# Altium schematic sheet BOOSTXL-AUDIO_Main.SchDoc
size 431 x 279 mm; Date: Not shown in title block; ApprovedBy: Not shown in title block; CheckedBy: Not shown in title block; Author: Not shown in title block; CompanyName: Not shown in title block; Engineer: Not shown in title block; Organization: Not shown in title block; Address1: Not shown in title block; Address2: Not shown in title block; Address3: Not shown in title block; Address4: Not shown in title block; DocumentNumber: 1; Revision: Use project parameter SCH_Rev; SheetNumber: 1; SheetTotal: 2; PageSetup: Record=PageOptions¦CenterHorizontal=True¦CenterVertical=True¦PrintScale=0.62¦XCorrection=1.00¦YCorrection=1.00¦PrintKind=0¦BorderSize=5000000¦LeftOffset=0¦BottomOffset=0¦Orientation=2¦PaperLength=1000¦PaperWidth=1000¦Scale=100¦PaperSource=15¦PrintQuality=600¦MediaType=1¦DitherType=10¦PrintScaleMode=1¦PaperKind=Letter
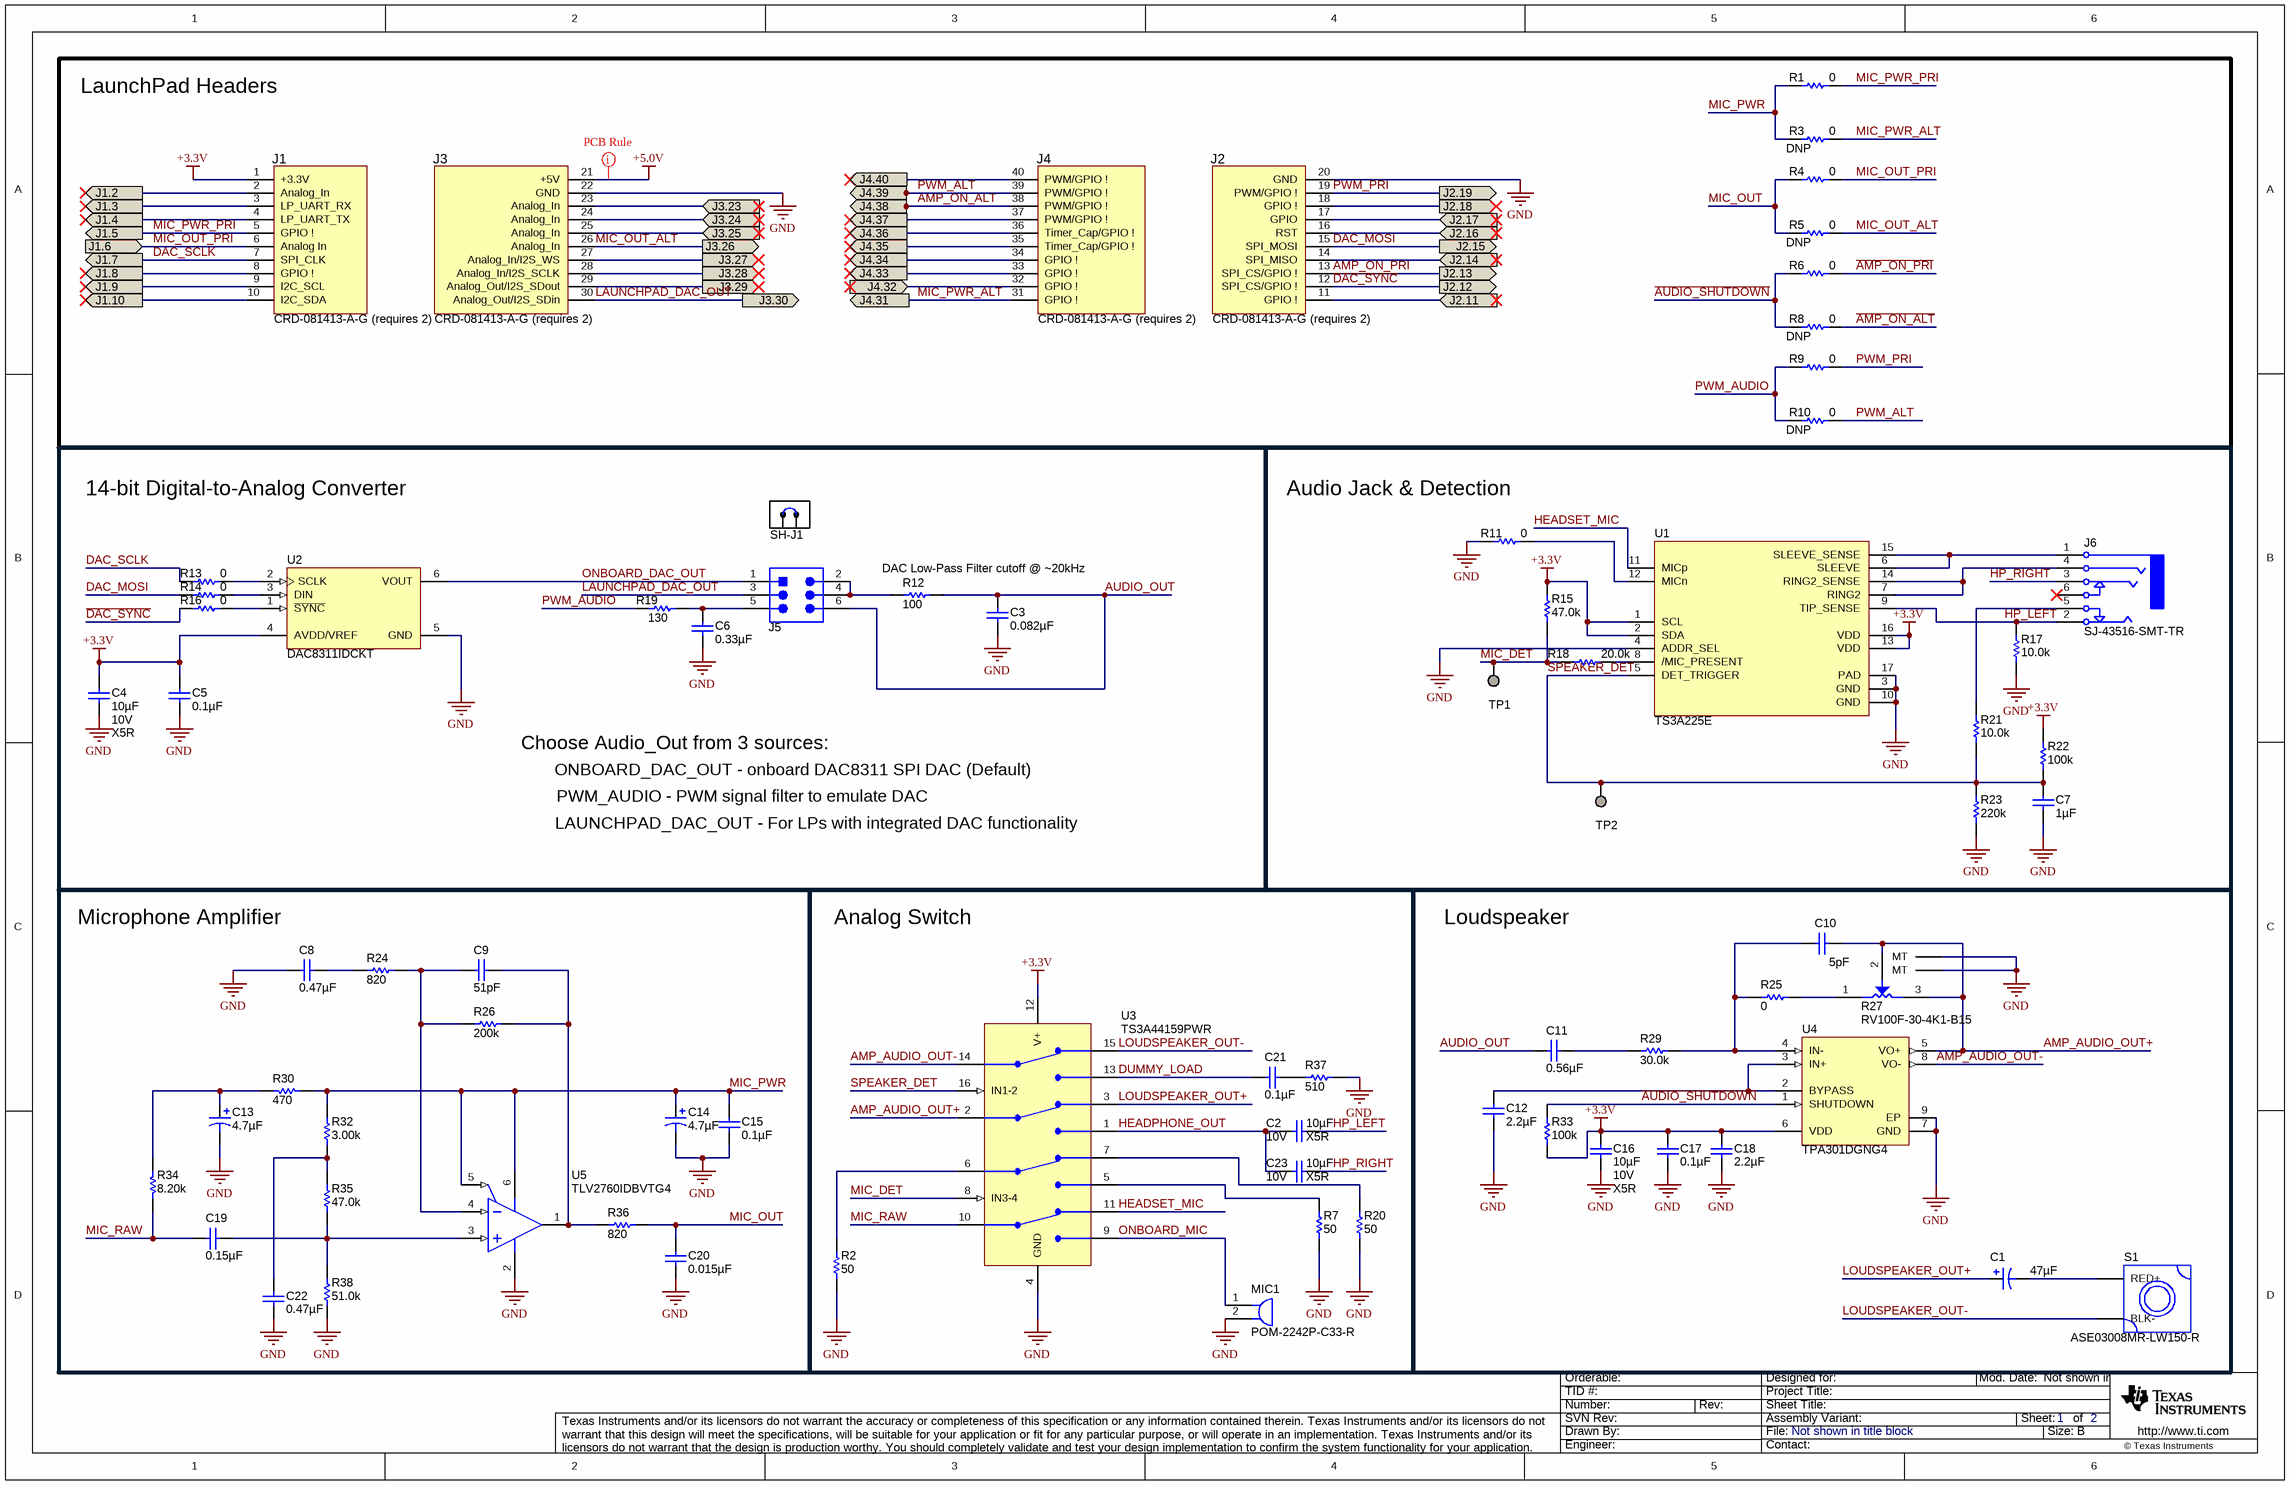
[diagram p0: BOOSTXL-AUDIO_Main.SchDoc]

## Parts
C1  ValueDisplayed: 47µF  [3528-21]  (hidden comment: TPSB476K010R0250)
C2  ValueDisplayed: 10µF  Value2: 10V  TempCo: X5R  [0603]  (hidden comment: C1608X5R1A106M)
C3  ValueDisplayed: 0.082µF  [0603]  (hidden comment: GRM188R71C823KA01D)
C4  ValueDisplayed: 10µF  Value2: 10V  TempCo: X5R  [0603]  (hidden comment: C1608X5R1A106M)
C5  ValueDisplayed: 0.1µF  [0603]  (hidden comment: GRM188R70J104KA01D)
C6  ValueDisplayed: 0.33µF  [0603]  (hidden comment: C0603C334K8RACTU)
C7  ValueDisplayed: 1µF  [0603]  (hidden comment: GRM188R71C105KA12D)
C8  ValueDisplayed: 0.47µF  [0603]  (hidden comment: GRM188R60J474KA01D)
C9  ValueDisplayed: 51pF  [0603]  (hidden comment: GRM1885C2A510JA01D)
C10  ValueDisplayed: 5pF  [0603]  (hidden comment: CC0603CRNPO9BN5R0)
C11  ValueDisplayed: 0.56µF  [0603]  (hidden comment: GRM188R71A564KA61D)
C12  ValueDisplayed: 2.2µF  [0603]  (hidden comment: GRM188R61A225KE34D)
C13  ValueDisplayed: 4.7µF  [3216-18]  (hidden comment: TPSA475K010R1400)
C14  ValueDisplayed: 4.7µF  [3216-18]  (hidden comment: TPSA475K010R1400)
C15  ValueDisplayed: 0.1µF  [0603]  (hidden comment: GRM188R70J104KA01D)
C16  ValueDisplayed: 10µF  Value2: 10V  TempCo: X5R  [0603]  (hidden comment: C1608X5R1A106M)
C17  ValueDisplayed: 0.1µF  [0603]  (hidden comment: GRM188R70J104KA01D)
C18  ValueDisplayed: 2.2µF  [0603]  (hidden comment: GRM188R61A225KE34D)
C19  ValueDisplayed: 0.15µF  [0603]  (hidden comment: GRM188R61A154KA01D)
C20  ValueDisplayed: 0.015µF  [0603]  (hidden comment: C0603C153K1RACTU)
C21  ValueDisplayed: 0.1µF  [0603]  (hidden comment: GRM188R70J104KA01D)
C22  ValueDisplayed: 0.47µF  [0603]  (hidden comment: GRM188R60J474KA01D)
C23  ValueDisplayed: 10µF  Value2: 10V  TempCo: X5R  [0603]  (hidden comment: C1608X5R1A106M)
J1  CRD-081413-A-G (requires 2)  [40Pin BP]  (parts A,B,C,D of 4)
J5  PBC03DAAN  [Sullins_PBC03DAAN]  (value not drawn)
J6  SJ-43516-SMT-TR  [CUI_SJ-43516-SMT]
MIC1  POM-2242P-C33-R  [MIC_POM-2242P-C33-R]
R1  ValueDisplayed: 0  [0603]  (hidden comment: CRCW06030000Z0EA)
R2  ValueDisplayed: 50  [0603]  (hidden comment: CRCW060350R0FKEA)
R3  ValueDisplayed: 0  [0603]  (hidden comment: CRCW06030000Z0EA)
R4  ValueDisplayed: 0  [0603]  (hidden comment: CRCW06030000Z0EA)
R5  ValueDisplayed: 0  [0603]  (hidden comment: CRCW06030000Z0EA)
R6  ValueDisplayed: 0  [0603]  (hidden comment: CRCW06030000Z0EA)
R7  ValueDisplayed: 50  [0603]  (hidden comment: CRCW060350R0FKEA)
R8  ValueDisplayed: 0  [0603]  (hidden comment: CRCW06030000Z0EA)
R9  ValueDisplayed: 0  [0603]  (hidden comment: CRCW06030000Z0EA)
R10  ValueDisplayed: 0  [0603]  (hidden comment: CRCW06030000Z0EA)
R11  ValueDisplayed: 0  [0603]  (hidden comment: CRCW06030000Z0EA)
R12  ValueDisplayed: 100  [0603]  (hidden comment: RC0603FR-07100RL)
R13  ValueDisplayed: 0  [0603]  (hidden comment: CRCW06030000Z0EA)
R14  ValueDisplayed: 0  [0603]  (hidden comment: CRCW06030000Z0EA)
R15  ValueDisplayed: 47.0k  [0603]  (hidden comment: RC0603FR-0747KL)
R16  ValueDisplayed: 0  [0603]  (hidden comment: CRCW06030000Z0EA)
R17  ValueDisplayed: 10.0k  [0603]  (hidden comment: RC0603FR-0710KL)
R18  ValueDisplayed: 20.0k  [0603]  (hidden comment: RC0603FR-0720KL)
R19  ValueDisplayed: 130  [0603]  (hidden comment: RC0603FR-07130RL)
R20  ValueDisplayed: 50  [0603]  (hidden comment: CRCW060350R0FKEA)
R21  ValueDisplayed: 10.0k  [0603]  (hidden comment: RC0603FR-0710KL)
R22  ValueDisplayed: 100k  [0603]  (hidden comment: CRCW0603100KFKEA)
R23  ValueDisplayed: 220k  [0603]  (hidden comment: RC0603FR-07220KL)
R24  value 820  [0603]  (hidden comment: RC0603FR-07820RL)
R25  ValueDisplayed: 0  [0603]  (hidden comment: CRCW06030000Z0EA)
R26  ValueDisplayed: 200k  [0603]  (hidden comment: RC0603FR-07200KL)
R27  RV100F-30-4K1-B15  [RV100F-30-4K1-B15]
R29  ValueDisplayed: 30.0k  [0603]  (hidden comment: RC0603FR-0730KL)
R30  value 470  [0603]  (hidden comment: RC0603FR-07470RL)
R32  ValueDisplayed: 3.00k  [0603]  (hidden comment: RC0603FR-073KL)
R33  ValueDisplayed: 100k  [0603]  (hidden comment: CRCW0603100KFKEA)
R34  value 8.20k  [0603]  (hidden comment: RC0603FR-078K2L)
R35  ValueDisplayed: 47.0k  [0603]  (hidden comment: RC0603FR-0747KL)
R36  value 820  [0603]  (hidden comment: RC0603FR-07820RL)
R37  ValueDisplayed: 510  [0603]  (hidden comment: RC0603FR-07510RL)
R38  ValueDisplayed: 51.0k  [0603]  (hidden comment: RC0603FR-0751KL)
S1  ASE03008MR-LW150-R  [ASE03008MR-LW150-R]
SH-J1  969102-0000-DA  [SNT-100-BK-G]  (value not drawn)
TP1  TESTPOINT  [TP_H045P075]  (value not drawn)  (no BOM)
TP2  TESTPOINT  [TP_H045P075]  (value not drawn)  (no BOM)
U1  TS3A225E  [QFN-16 (RTE)]
U2  DAC8311IDCKT  [TI-DCK6_V]
U3  TS3A44159PWR  [PW0016A_N]
U4  TPA301DGNG4  [TI-DGN8-1760X1425TP_M]
U5  TLV2760IDBVTG4  [DBV0006A_N]

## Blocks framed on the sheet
LaunchPad Headers: J1 R1 R3-R6 R8-R10
14-bit Digital-to-Analog Converter: C3-C6 J5 R12-R14 R16 R19 SH-J1 U2
Audio Jack & Detection: C7 J6 R11 R15 R17 R18 R21-R23 TP1 TP2 U1
Microphone Amplifier: C8 C9 C13-C15 C19 C20 C22 R24 R26 R30 R32 R34-R36 R38 U5
Analog Switch: C2 C21 C23 MIC1 R2 R7 R20 R37 U3
Loudspeaker: C1 C10-C12 C16-C18 R25 R27 R29 R33 S1 U4

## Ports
J1.2, J1.3, J1.4, J1.5 (out), J1.6 (in), J1.7 (out), J1.8, J1.9, J1.10, J2.11, J2.12 (out), J2.13 (out), J2.14, J2.15 (out), J2.16, J2.17, J2.18 (out), J2.19 (out), J3.23, J3.24, J3.25, J3.26 (out), J3.27 (out), J3.28 (out), J3.29 (out), J3.30 (out), J4.31 (out), J4.32 (in), J4.33, J4.34, J4.35, J4.36, J4.37, J4.38 (out), J4.39 (out), J4.40

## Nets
+3.3V: C4.1 C5.1 C16.2 C17.2 C18.1 J1.1(+3.3V) R15.1 R22.1 R33.1 U1.1(SCL) U1.2(SDA) U1.13(VDD) U1.16(VDD) U2.4(AVDD/VREF) U3.12(V+) U4.6(VDD)
+5.0V: J1.21(+5V)
GND: C3.1 C4.2 C5.2 C6.2 C7.1 C8.1 C12.2 C13.2(-) C14.2(-) C15.2 C16.1 C17.1 C18.2 C20.2 C22.1 J1.20(GND) J1.22(GND) MIC1.2 R2.2 R7.2 R11.1 R17.2 R20.2 R23.2 R27.GND(MT) R37.1 R38.1 U1.3(GND) U1.4(ADDR_SEL) U1.10(GND) U1.17(PAD) U2.5(GND) U3.4(GND) U4.7(GND) U4.9(EP) U5.2(GND)
~{AMP_ON_ALT}: J1.38(PWM/GPIO_!) R8.2 ; port J4.38
~{AMP_ON_PRI}: J1.13(SPI_CS/GPIO_!) R6.2 ; port J2.13
~{AUDIO_SHUTDOWN}: R6.1 R8.1 R33.2 U4.1(SHUTDOWN)
~{DAC_SYNC}: J1.12(SPI_CS/GPIO_!) R16.1 ; port J2.12
AMP_AUDIO_OUT+: C10.2 R27.2(A2) R27.3(A3) U3.2(COM2) U4.5(VO+)
AMP_AUDIO_OUT-: U3.14(COM1) U4.8(VO-)
AUDIO_OUT: C3.2 C11.2 J5.6 R12.2
DAC_MOSI: J1.15(SPI_MOSI) R14.1 ; port J2.15
DAC_SCLK: J1.7(SPI_CLK) R13.1 ; port J1.7
DUMMY_LOAD: C21.2 U3.13(NO1)
HEADPHONE_OUT: C2.1 C23.1 U3.1(NO2)
HEADSET_MIC: U1.11(MICp) U3.11(NC4)
HP_LEFT: C2.2 J6.2(TIP) R17.1 U1.9(TIP_SENSE)
HP_RIGHT: C23.2 J6.3(RING_1)
J1.2: J1.2(Analog_In) ; port J1.2
J1.3: J1.3(LP_UART_RX) ; port J1.3
J1.4: J1.4(LP_UART_TX) ; port J1.4
J1.8: J1.8(GPIO_!) ; port J1.8
J1.9: J1.9(I2C_SCL) ; port J1.9
J1.10: J1.10(I2C_SDA) ; port J1.10
J2.11: J1.11(GPIO_!) ; port J2.11
J2.14: J1.14(SPI_MISO) ; port J2.14
J2.16: J1.16(RST) ; port J2.16
J2.17: J1.17(GPIO) ; port J2.17
J2.18: J1.18(GPIO_!) ; port J2.18
J3.23: J1.23(Analog_In) ; port J3.23
J3.24: J1.24(Analog_In) ; port J3.24
J3.25: J1.25(Analog_In) ; port J3.25
J3.27: J1.27(Analog_In/I2S_WS) ; port J3.27
J3.28: J1.28(Analog_In/I2S_SCLK) ; port J3.28
J3.29: J1.29(Analog_Out/I2S_SDout) ; port J3.29
J4.32: J1.32(GPIO_!) ; port J4.32
J4.33: J1.33(GPIO_!) ; port J4.33
J4.34: J1.34(GPIO_!) ; port J4.34
J4.35: J1.35(Timer_Cap/GPIO_!) ; port J4.35
J4.36: J1.36(Timer_Cap/GPIO_!) ; port J4.36
J4.37: J1.37(PWM/GPIO_!) ; port J4.37
J4.40: J1.40(PWM/GPIO_!) ; port J4.40
LAUNCHPAD_DAC_OUT: J1.30(Analog_Out/I2S_SDin) J5.3 ; port J3.30
LOUDSPEAKER_OUT+: C1.1(+) U3.3(NC2)
LOUDSPEAKER_OUT-: S1.2(BLK-) U3.15(NC1)
MIC_DET: R15.2 R18.1 TP1.1 U3.8(IN3-4)
MIC_OUT: C20.1 R4.1 R5.1 R36.2
MIC_OUT_ALT: J1.26(Analog_In) R5.2 ; port J3.26
MIC_OUT_PRI: J1.6(Analog_In) R4.2 ; port J1.6
MIC_PWR: C14.1(+) C15.1 R1.1 R3.1 R30.1 R32.2 U5.5(~{SHDN}) U5.6(VDD)
MIC_PWR_ALT: J1.31(GPIO_!) R3.2 ; port J4.31
MIC_PWR_PRI: J1.5(GPIO_!) R1.2 ; port J1.5
MIC_RAW: C19.1 R34.1 U3.10(COM4)
ONBOARD_DAC_OUT: J5.1 U2.6(VOUT)
ONBOARD_MIC: MIC1.1 U3.9(NO4)
PWM_ALT: J1.39(PWM/GPIO_!) R10.2 ; port J4.39
PWM_AUDIO: R9.1 R10.1 R19.1
PWM_PRI: J1.19(PWM/GPIO_!) R9.2 ; port J2.19
SPEAKER_DET: C7.2 R21.2 R22.2 R23.1 TP2.1 U1.5(DET_TRIGGER) U3.16(IN1-2)
NetC1_2: C1.2(-) S1.1(RED+)
NetC6_1: C6.1 J5.5 R19.2
NetC8_2: C8.2 R24.2
NetC9_1: C9.1 R24.1 R26.1 U5.4(IN-)
NetC9_2: C9.2 R26.2 R36.1 U5.1(OUT)
NetC10_1: C10.1 R25.1 R29.2 U4.4(IN-)
NetC11_1: C11.1 R29.1
NetC12_1: C12.1 U4.2(BYPASS) U4.3(IN+)
NetC13_1: C13.1(+) R30.2 R34.2
NetC19_2: C19.2 R35.1 R38.2 U5.3(IN+)
NetC21_1: C21.1 R37.2
NetC22_2: C22.2 R32.1 R35.2
NetJ5_2: J5.2 J5.4 R12.1
NetJ6_1: J6.1(SLEEVE) U1.6(SLEEVE) U1.15(SLEEVE_SENSE)
NetJ6_4: J6.4(RING_2) U1.7(RING2) U1.14(RING2_SENSE)
NetJ6_5: J6.5(TIP_SWITCH) R21.1
NetR2_1: R2.1 U3.6(COM3)
NetR7_1: R7.1 U3.5(NO3)
NetR11_2: R11.2 U1.12(MICn)
NetR13_2: R13.2 U2.2(SCLK)
NetR14_2: R14.2 U2.3(DIN)
NetR16_2: R16.2 U2.1(~{SYNC})
NetR18_2: R18.2 U1.8(/MIC_PRESENT)
NetR20_1: R20.1 U3.7(NC3)
NetR25_2: R25.2 R27.1(A1)

Not connected (* = marked no-connect by the designer): J6 6(RING_SWITCH)*

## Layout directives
rule Width Constraint [Pref Width = 15mil    Min Width = 15mil    Max Width = 20mil]: +5.0V

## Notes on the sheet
- (near J1) J1
- J3
- (near J1) J4
- J2
- DAC Low-Pass Filter cutoff @ |0kHz
- Choose Audio_Out from 3 sources:
- ONBOARD_DAC_OUT - onboard DAC8311 SPI DAC (Default)
- PWM_AUDIO - PWM signal filter to emulate DAC
- LAUNCHPAD_DAC_OUT - For LPs with integrated DAC functionality

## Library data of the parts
C1 = TPSB476K010R0250: CAP, TA, 47 µF, 10 V, +/- 10%, 0.25 ohm, SMD; Manufacturer: AVX; Polarized: Y; CompType: Capacitor; Value: 47uF; U/M: EA; Cap_F: 0.000047; Tolerance_%: 10; Value2: 10V; ESR_ohm: 0.25; IRMS_A: 0.525; TaMin_C: -55; TaMax_C: 125; Cap_Case: B
C2 C4 C16 C23 = C1608X5R1A106M: CAP, CERM, 10 µF, 10 V, +/- 20%, X5R, 0603; Manufacturer: TDK; Polarized: N; CompType: Capacitor; Value: 10uF; U/M: EA; Cap_F: 0.00001; Tolerance_%: 20; ESR_ohm: 0.0078; Value1: 0.0078 ohm; VDC_V: 10; IRMS_A: 1.85; TaMin_C: -55; TaMax_C: 85
C3 = GRM188R71C823KA01D: CAP, CERM, 0.082 µF, 16 V, +/- 10%, X7R, 0603; Manufacturer: MuRata; Polarized: N; CompType: Capacitor; Value: 0.082uF; U/M: EA; Cap_F: 0.000000082; Tolerance_%: 10; Value1: Unknown; VDC_V: 16; Value2: 16V; TaMin_C: -55; TaMax_C: 125
C5 C15 C17 C21 = GRM188R70J104KA01D: CAP, CERM, 0.1uF, 6.3V, +/-10%, X7R, 0603; Manufacturer: MuRata; Polarized: N; CompType: Capacitor; U/M: EA; Cap_F: 0.0000001; Tolerance_%: 10; Value1: Unknown; VDC_V: 6.3; TaMin_C: -55; TaMax_C: 125
C6 = C0603C334K8RACTU: CAP, CERM, 0.33 µF, 10 V, +/- 10%, X7R, 0603; Manufacturer: Kemet; Polarized: N; CompType: Capacitor; Value: 0.33uF; U/M: EA; Cap_F: 0.00000033; Tolerance_%: 10; Value1: Unknown; Value2: 10V; TaMin_C: -55; TaMax_C: 125
C7 = GRM188R71C105KA12D: CAP, CERM, 1 µF, 16 V, +/- 10%, X7R, 0603; Manufacturer: MuRata; Polarized: N; CompType: Capacitor; Value: 1uF; U/M: EA; Cap_F: 0.000001; Tolerance_%: 10; ESR_ohm: 0.011; Value1: 0.011 ohm; VDC_V: 16; Value2: 16V; TaMin_C: -55; TaMax_C: 125
C8 C22 = GRM188R60J474KA01D: CAP, CERM, 0.47uF, 6.3V, +/-10%, X5R, 0603; Manufacturer: MuRata; Polarized: N; CompType: Capacitor; U/M: EA; Cap_F: 0.00000047; Tolerance_%: 10; Value1: Unknown; VDC_V: 6.3; TaMin_C: -55; TaMax_C: 85
C9 = GRM1885C2A510JA01D: CAP, CERM, 51 pF, 100 V, +/- 5%, C0G/NP0, 0603; Manufacturer: MuRata; Polarized: N; CompType: Capacitor; Value: 51pF; U/M: EA; Cap_F: 0.000000000051; Tolerance_%: 5; Value1: Unknown; VDC_V: 100; Value2: 100V; TaMin_C: -55; TaMax_C: 125
C10 = Capacitor: CAP, CERM, 5 pF, 50 V, +/- 5%, C0G/NP0, 0603; Manufacturer: Yageo America; Polarized: N; Value: 5pF; U/M: EA; Cap_F: 0.000000000005; TaMax_C: 125; TaMin_C: -55; Tolerance_%: 5; Value1: Unknown; Value2: 50V; VDC_V: 50
C11 = GRM188R71A564KA61D: CAP, CERM, 0.56 µF, 10 V, +/- 10%, X7R, 0603; Manufacturer: MuRata; Polarized: N; CompType: Capacitor; Value: 0.56uF; U/M: EA; Cap_F: 0.00000056; Tolerance_%: 10; Value1: Unknown; Value2: 10V; TaMin_C: -55; TaMax_C: 125; AEC Category: Q200
C12 C18 = GRM188R61A225KE34D: CAP, CERM, 2.2 µF, 10 V, +/- 10%, X5R, 0603; Manufacturer: MuRata; Polarized: N; CompType: Capacitor; Value: 2.2uF; U/M: EA; Cap_F: 0.0000022; Tolerance_%: 10; Value1: Unknown; Value2: 10V; TaMin_C: -55; TaMax_C: 85
C13 C14 = TPSA475K010R1400: CAP, TA, 4.7 µF, 10 V, +/- 10%, 1.4 ohm, SMD; Manufacturer: AVX; Polarized: Y; CompType: Capacitor; Value: 4.7uF; U/M: EA; Cap_F: 0.0000047; Tolerance_%: 10; Value1: 1.4 ohm; Value2: 10V; ESR_ohm: 1.4; IRMS_A: 0.208; TaMin_C: -55; TaMax_C: 125; Cap_Case: A
C19 = GRM188R61A154KA01D: CAP, CERM, 0.15uF, 10V, +/-10%, X5R, 0603; Manufacturer: MuRata; Polarized: N; CompType: Capacitor; U/M: EA; Cap_F: 0.00000015; Tolerance_%: 10; Value1: Unknown; TaMin_C: -55; TaMax_C: 85
C20 = C0603C153K1RACTU: CAP, CERM, 0.015 µF, 100 V, +/- 10%, X7R, 0603; Manufacturer: Kemet; Polarized: N; CompType: Capacitor; Value: 0.015uF; U/M: EA; Cap_F: 0.000000015; Tolerance_%: 10; Value1: Unknown; VDC_V: 100; Value2: 100V; TaMin_C: -55; TaMax_C: 125
J1 = 40Pin Booster Pack Connection: Manufacturer: MLE; SymbolCreator: a0272566; CompType: Long Lead Header; U/M: EA, IN, or GM
J5 = PBC03DAAN: Header, 100mil, 3x2, Gold, TH; Manufacturer: Sullins Connector Solutions; SymbolCreator: a0412235; U/M: EA
J6 = SJ-43516-SMT-TR: AUDIO JACK 3.5mm 4COND, SMT; Manufacturer: CUI Inc.; SymbolCreator: Altium; U/M: EA
MIC1 = POM-2242P-C33-R: Microphone, Condenser, Analog, Omnidirectional, -42DB, TH; Manufacturer: PUI Audio; SymbolCreator: a0412235
R1 R3-R6 R8-R11 R13 R14 R16 R25 = CRCW06030000Z0EA: RES, 0, 5%, 0.1 W, 0603; Manufacturer: Vishay-Dale; CompType: Resistor; Value: 0; Value_Code: 0000; Tolerance_%: 5; Power_W: 0.1; Value2: 0.1W; VDC_V: 75; TempCo: 200 ppm/C; EIA_Code: E24; U/M: EA
R2 R7 R20 = CRCW060350R0FKEA: RES, 50, 1%, 0.1 W, 0603; Manufacturer: Vishay-Dale; CompType: Resistor; Value: 50; Value_Code: 50R0; Tolerance_%: 1; Power_W: 0.1; Value2: 0.1W; VDC_V: 75; TempCo: 100 ppm/C; U/M: EA
R12 = RC0603FR-07100RL: RES, 100, 1%, 0.1 W, 0603; Manufacturer: Yageo America; CompType: Resistor; Value: 100; Value_Code: 100R; Tolerance_%: 1; Power_W: 0.1; Value2: 0.1W; VDC_V: 150; TempCo: 200 ppm/C; EIA_Code: E96; U/M: EA
R15 R35 = RC0603FR-0747KL: RES, 47.0 k, 1%, 0.1 W, 0603; Manufacturer: Yageo America; CompType: Resistor; Value: 47.0k; Res_ohm: 47000; Value_Code: 47k0; Tolerance_%: 1; Power_W: 0.1; Value2: 0.1W; VDC_V: 150; TempCo: 200 ppm/C; U/M: EA
R17 R21 = RC0603FR-0710KL: RES, 10.0 k, 1%, 0.1 W, 0603; Manufacturer: Yageo America; CompType: Resistor; Value: 10.0k; Res_ohm: 10000; Value_Code: 10k0; Tolerance_%: 1; Power_W: 0.1; Value2: 0.1W; VDC_V: 150; TempCo: 200 ppm/C; EIA_Code: E96; U/M: EA
R18 = RC0603FR-0720KL: RES, 20.0 k, 1%, 0.1 W, 0603; Manufacturer: Yageo America; CompType: Resistor; Value: 20.0k; Res_ohm: 20000; Value_Code: 20k0; Tolerance_%: 1; Power_W: 0.1; Value2: 0.1W; VDC_V: 150; TempCo: 200 ppm/C; EIA_Code: E96; U/M: EA
R19 = RC0603FR-07130RL: RES, 130, 1%, 0.1 W, 0603; Manufacturer: Yageo America; CompType: Resistor; Value: 130; Value_Code: 130R; Tolerance_%: 1; Power_W: 0.1; Value2: 0.1W; VDC_V: 150; TempCo: 200 ppm/C; EIA_Code: E96; U/M: EA
R22 R33 = CRCW0603100KFKEA: RES, 100 k, 1%, 0.1 W, 0603; Manufacturer: Vishay-Dale; CompType: Resistor; Value: 100k; Res_ohm: 100000; Tolerance_%: 1; Power_W: 0.1; Value2: 0.1W; VDC_V: 75; TempCo: 100 ppm/C; EIA_Code: E96; U/M: EA
R23 = RC0603FR-07220KL: RES, 220 k, 1%, 0.1 W, 0603; Manufacturer: Yageo America; CompType: Resistor; Value: 220k; Res_ohm: 220000; Tolerance_%: 1; Power_W: 0.1; Value2: 0.1W; VDC_V: 150; TempCo: 200 ppm/C; U/M: EA
R24 R36 = RC0603FR-07820RL: RES, 820 ohm, 1%, 0.1W, 0603; Manufacturer: Yageo America; CompType: Resistor; Value_Code: 820R; Tolerance_%: 1; Power_W: 0.1; VDC_V: 150; TempCo: 200 ppm/C; U/M: EA
R26 = RC0603FR-07200KL: RES, 200 k, 1%, 0.1 W, 0603; Manufacturer: Yageo America; CompType: Resistor; Value: 200k; Res_ohm: 200000; Tolerance_%: 1; Power_W: 0.1; Value2: 0.1W; VDC_V: 150; TempCo: 200 ppm/C; EIA_Code: E96; U/M: EA
R27 = RV100F-30-4K1-B15: Potentiometers 10mm Linear 100K PC Mount; Manufacturer: Alpha (Taiwan); Alternate Manufacturer: Any; Alternate PartNumber: Equivalent; CompType: Pot; U/M: EA
R29 = RC0603FR-0730KL: RES, 30.0 k, 1%, 0.1 W, 0603; Manufacturer: Yageo America; CompType: Resistor; Value: 30.0k; Res_ohm: 30000; Value_Code: 30k0; Tolerance_%: 1; Power_W: 0.1; Value2: 0.1W; VDC_V: 150; TempCo: 200 ppm/C; U/M: EA; AEC Category: Q200
R30 = RC0603FR-07470RL: RES, 470 ohm, 1%, 0.1W, 0603; Manufacturer: Yageo America; CompType: Resistor; Value_Code: 470R; Tolerance_%: 1; Power_W: 0.1; VDC_V: 150; TempCo: 200 ppm/C; U/M: EA
R32 = RC0603FR-073KL: RES, 3.00 k, 1%, 0.1 W, 0603; Manufacturer: Yageo America; CompType: Resistor; Value: 3.00k; Res_ohm: 3000; Value_Code: 3k00; Tolerance_%: 1; Power_W: 0.1; Value2: 0.1W; VDC_V: 150; TempCo: 200 ppm/C; U/M: EA
R34 = RC0603FR-078K2L: RES, 8.20k ohm, 1%, 0.1W, 0603; Manufacturer: Yageo America; CompType: Resistor; Res_ohm: 8200; Value_Code: 8k20; Tolerance_%: 1; Power_W: 0.1; VDC_V: 150; TempCo: 200 ppm/C; U/M: EA
R37 = RC0603FR-07510RL: RES, 510, 1%, 0.1 W, 0603; Manufacturer: Yageo America; CompType: Resistor; Value: 510; Value_Code: 510R; Tolerance_%: 1; Power_W: 0.1; Value2: 0.1W; VDC_V: 150; TempCo: 200 ppm/C; U/M: EA
R38 = RC0603FR-0751KL: RES, 51.0 k, 1%, 0.1 W, 0603; Manufacturer: Yageo America; CompType: Resistor; Value: 51.0k; Res_ohm: 51000; Value_Code: 51k0; Tolerance_%: 1; Power_W: 0.1; Value2: 0.1W; VDC_V: 150; TempCo: 200 ppm/C; U/M: EA
S1 = PUI Speaker Enclosure: PUI SPEAKER ENCLOSURE 1 W 8 OHM 83 D; Manufacturer: PUI Audio; SymbolVersion: use current date i.e. 2008-05-20; SymbolCreator: a0866890; CompType: Header; U/M: EA
SH-J1 = 969102-0000-DA: Shunt, 100mil, Gold plated, Black; Manufacturer: 3M; Alternate Manufacturer: Samtec; Value: 1x2; Note: You can "mate" this to a header by matching the designator.  i.e. use SH-J3 for header J3
TP1 TP2 = TP_H0.45P0.75: Manufacturer: Texas Instruments; CompType: Pad
U1 = TS3A225E: Autonomous Audio Switch with Headset Type Detection; Manufacturer: Texas Instruments; SymbolVersion: use current date i.e. 2008-05-20; SymbolCreator: Use LDAP id; CompType: Used in some BOM reports.  Useful for finding later.; U/M: EA, IN, or GM
U2 = CMP-0004-00352-1: 14-Bit, Single Channel, 80 uA, 1.8 to 5.5 V DAC, -40 to 125 degC, 6-pin SOT23 (DCK6), Green (RoHS & no Sb/Br); Manufacturer: Texas Instruments; Settling Time(us): 6; Interface: Serial SPI; INL(Max)(+/-LSB): 4; SNR(dB): 88; Resolution(Bits): 14; Power Consumption(Typ)(mW): 0.14; DNL(Max)(+/-LSB): 1; SubFamily: Precision DAC (=<10MSPS); SFDR(dB): 66
U3 = TS3A44159PWR: 0.45 ohm QUAD SPDT ANALOG SWITCH QUAD-CHANNEL 2:1 MULTIPLEXER/DEMULTIPLEXER WITH TWO CONTROLS, PW0016A; Manufacturer: Texas Instruments; SymbolCreator: a0411947; CompType: IC; U/M: EA
U4 = CMP-0991-00051-1: 350-mW Mono Class-AB Audio Amplifier, -40 to 85 degC, 8-pin SOP (DGN8), Green (RoHS & no Sb/Br); Manufacturer: Texas Instruments; Supply Min(Min)(Volt): 2.5; PSRR(dB): 78; Supply Max(Max)(Volt): 5.5; Output Power(W): 0.35; SubFamily: Dynamic Speaker
U5 = TLV2760IDBVTG4: Single MicroPower, Rail-to-Rail, Single Supply Amplifier with Shutdown, 1.8 to 3.6 V, -40 to 85 degC, 6-pin SOT23 (DBV0006A), Green (RoHS & no Sb/Br); Manufacturer: Texas Instruments; Alternate Manufacturer: None; Alternate PartNumber: Equivalent; CMRR(Min)(dB): 50; GBW(Typ)(MHz): 0.5; IIB(Max)(pA): 15; Iq per channel(Max)(mA): 0.028; Number of Channels: 1; Offset Drift(Typ)(uV/C): 9; Packing: SMALL T&R; Rating: Catalog; Slew Rate(Typ)(V/us): 0.2; Sub Family: Low Power Amp (<=500uA), Low Supply Voltage Amplifier (<=2.7V), Precision Amplifier; Total Supply Voltage(Max)(+5V is 5, +/-5V is 10): 3.6; Total Supply Voltage(Min)(+5V is 5, +/-5V is 10): 1.8; Vio (25C)(Max)(mV): 3.5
